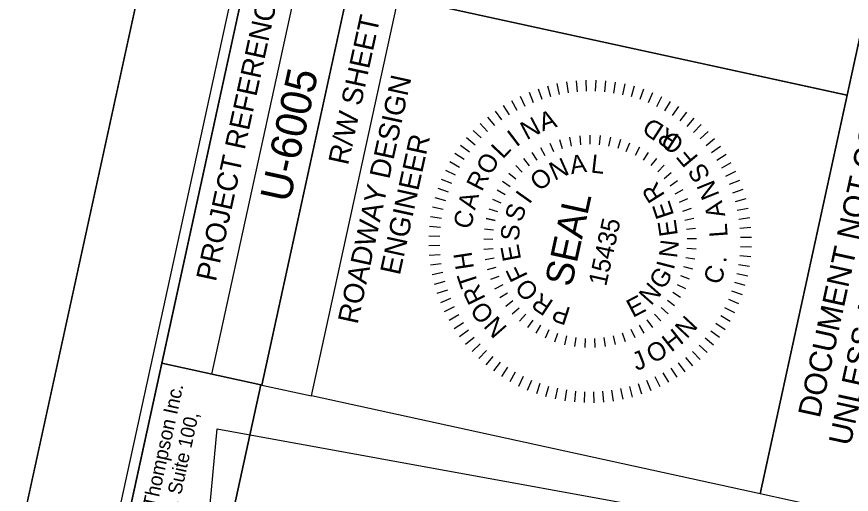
# Model space of a CAD drawing. Extents: x 1615716 to 1617263, y 900664 to 902742.
# Drawn here: x 1616130.6 to 1616335.1, y 902294.3 to 902411.4 of the extents above; entities that cross this region are included whole.
import ezdxf

# ---------------------------------------------------------------- set-up
doc = ezdxf.new("R2010")
doc.units = 0
for name, color, linetype in [('Default', 7, 'Continuous'), ('Exist Plan Preparation Watershed Blue', 7, 'Continuous'), ('Exist Structure Minor Pipes RCP 18 Inch', 7, 'Continuous'), ('Prop Drainage Structure Plot Symbol 20 Scale', 7, 'Continuous'), ('Prop EOT', 7, 'Continuous'), ('Prop SS Cut Line', 7, 'Continuous'), ('Prop SS Cut Text', 7, 'Continuous'), ('Prop SS Fill Line', 7, 'Continuous'), ('Prop SS Fill Text', 7, 'Continuous'), ('Prop SS Transition Line', 7, 'Continuous')]:
    doc.layers.add(name, color=color, linetype=linetype)

msp = doc.modelspace()

# ---------------------------------------------------------------- linework, layer by layer
at = {"layer": 'Default'}
msp.add_lwpolyline([(1616161.03, 902186.8), (1616190.38, 902321.16), (1616166.14, 902326.45), (1616136.79, 902192.09)], close=True, dxfattribs=at)
at = {"layer": 'Exist Plan Preparation Watershed Blue'}
for p, q in [((1616267.67, 902395.71), (1616267.9, 902393.02)), ((1616270.06, 902395.84), (1616270.13, 902393.15)), ((1616272.45, 902395.83), (1616272.35, 902393.14)), ((1616274.83, 902395.67), (1616274.57, 902392.99)), ((1616258.34, 902393.75), (1616259.21, 902391.2)), ((1616260.63, 902394.45), (1616261.34, 902391.85)), ((1616262.95, 902395.01), (1616263.5, 902392.37)), ((1616265.3, 902395.43), (1616265.7, 902392.76)), ((1616277.2, 902395.37), (1616276.78, 902392.71)), ((1616279.55, 902394.93), (1616278.97, 902392.3)), ((1616281.87, 902394.35), (1616281.13, 902391.76)), ((1616284.14, 902393.63), (1616283.25, 902391.08)), ((1616253.93, 902391.95), (1616255.09, 902389.52)), ((1616256.11, 902392.92), (1616257.13, 902390.42)), ((1616286.37, 902392.77), (1616285.33, 902390.29)), ((1616288.54, 902391.78), (1616287.35, 902389.36)), ((1616249.76, 902389.62), (1616251.21, 902387.35)), ((1616251.81, 902390.85), (1616253.12, 902388.49)), ((1616290.65, 902390.66), (1616289.32, 902388.32)), ((1616292.69, 902389.42), (1616291.21, 902387.16)), ((1616247.79, 902388.28), (1616249.37, 902386.1)), ((1616294.65, 902388.05), (1616293.04, 902385.88)), ((1616244.1, 902385.24), (1616245.94, 902383.27)), ((1616245.9, 902386.81), (1616247.61, 902384.73)), ((1616296.52, 902386.57), (1616294.79, 902384.5)), ((1616242.41, 902383.56), (1616244.36, 902381.7)), ((1616298.3, 902384.97), (1616296.44, 902383.02)), ((1616299.98, 902383.28), (1616298.01, 902381.44)), ((1616240.81, 902381.78), (1616242.88, 902380.04)), ((1616263.58, 902381.28), (1616264.23, 902379.13)), ((1616266.03, 902381.88), (1616266.46, 902379.68)), ((1616268.52, 902382.25), (1616268.73, 902380.01)), ((1616271.03, 902382.38), (1616271.03, 902380.13)), ((1616273.55, 902382.26), (1616273.33, 902380.02)), ((1616276.04, 902381.9), (1616275.61, 902379.69)), ((1616278.48, 902381.3), (1616277.85, 902379.14)), ((1616301.56, 902381.48), (1616299.48, 902379.77)), ((1616239.33, 902379.9), (1616241.49, 902378.3)), ((1616258.92, 902379.37), (1616259.97, 902377.39)), ((1616261.21, 902380.44), (1616262.06, 902378.36)), ((1616279.94, 902378.41), (1616280.78, 902380.49)), ((1616283.15, 902379.4), (1616282.11, 902377.42)), ((1616303.02, 902379.59), (1616300.84, 902378.01)), ((1616237.96, 902377.94), (1616240.22, 902376.47)), ((1616256.76, 902378.1), (1616257.99, 902376.22)), ((1616285.32, 902378.13), (1616284.09, 902376.25)), ((1616304.37, 902377.62), (1616302.1, 902376.17)), ((1616236.72, 902375.91), (1616239.06, 902374.57)), ((1616254.72, 902376.62), (1616256.13, 902374.86)), ((1616287.35, 902376.65), (1616285.95, 902374.9)), ((1616305.59, 902375.57), (1616303.24, 902374.26)), ((1616235.6, 902373.8), (1616238.02, 902372.61)), ((1616251.13, 902373.1), (1616252.84, 902371.65)), ((1616252.84, 902374.94), (1616254.41, 902373.34)), ((1616289.24, 902374.99), (1616287.68, 902373.38)), ((1616290.96, 902373.14), (1616289.25, 902371.69)), ((1616306.69, 902373.45), (1616304.27, 902372.28)), ((1616234.61, 902371.62), (1616237.09, 902370.58)), ((1616249.6, 902371.09), (1616251.45, 902369.82)), ((1616292.49, 902371.14), (1616290.65, 902369.87)), ((1616307.66, 902371.27), (1616305.17, 902370.25)), ((1616233.75, 902369.39), (1616236.29, 902368.51)), ((1616248.27, 902368.95), (1616250.24, 902367.86)), ((1616293.82, 902369.01), (1616291.86, 902367.91)), ((1616308.5, 902369.03), (1616305.95, 902368.16)), ((1616233.03, 902367.12), (1616235.62, 902366.38)), ((1616232.45, 902364.8), (1616235.08, 902364.22)), ((1616247.16, 902366.69), (1616249.22, 902365.8)), ((1616294.94, 902366.75), (1616292.88, 902365.85)), ((1616309.2, 902366.75), (1616306.6, 902366.04)), ((1616246.27, 902364.34), (1616248.41, 902363.65)), ((1616295.83, 902364.4), (1616293.7, 902363.7)), ((1616309.76, 902364.43), (1616307.12, 902363.88)), ((1616232, 902362.45), (1616234.67, 902362.03)), ((1616245.61, 902361.91), (1616247.8, 902361.43)), ((1616247.8, 902361.43), (1616245.61, 902361.91)), ((1616296.5, 902361.97), (1616294.3, 902361.48)), ((1616310.18, 902362.07), (1616307.51, 902361.68)), ((1616231.71, 902360.08), (1616234.39, 902359.83)), ((1616245.19, 902359.42), (1616247.42, 902359.16)), ((1616296.93, 902359.49), (1616294.69, 902359.21)), ((1616310.46, 902359.7), (1616307.77, 902359.47)), ((1616231.55, 902357.7), (1616234.24, 902357.61)), ((1616245.01, 902356.92), (1616247.26, 902356.86)), ((1616297.11, 902356.98), (1616294.86, 902356.92)), ((1616310.59, 902357.32), (1616307.89, 902357.25)), ((1616231.54, 902355.32), (1616234.23, 902355.38)), ((1616245.07, 902354.4), (1616247.32, 902354.56)), ((1616297.05, 902354.46), (1616294.81, 902354.62)), ((1616310.58, 902354.93), (1616307.88, 902355.03)), ((1616231.67, 902352.93), (1616234.36, 902353.16)), ((1616310.42, 902352.55), (1616307.74, 902352.81)), ((1616231.94, 902350.56), (1616234.61, 902350.95)), ((1616245.38, 902351.9), (1616247.59, 902352.28)), ((1616296.76, 902351.96), (1616294.54, 902352.34)), ((1616310.12, 902350.18), (1616307.46, 902350.6)), ((1616232.37, 902348.21), (1616235, 902348.76)), ((1616245.93, 902349.44), (1616248.09, 902350.03)), ((1616296.21, 902349.5), (1616294.05, 902350.09)), ((1616232.92, 902345.88), (1616235.53, 902346.6)), ((1616246.71, 902347.05), (1616248.81, 902347.84)), ((1616295.44, 902347.11), (1616293.34, 902347.9)), ((1616309.68, 902347.83), (1616307.05, 902348.41)), ((1616233.62, 902343.6), (1616236.18, 902344.47)), ((1616247.72, 902344.74), (1616249.73, 902345.74)), ((1616292.41, 902345.78), (1616294.43, 902344.78)), ((1616309.09, 902345.51), (1616306.5, 902346.25)), ((1616234.46, 902341.36), (1616236.95, 902342.38)), ((1616248.94, 902342.54), (1616250.85, 902343.73)), ((1616293.22, 902342.59), (1616291.3, 902343.78)), ((1616308.37, 902343.24), (1616305.83, 902344.13)), ((1616235.43, 902339.18), (1616237.86, 902340.35)), ((1616250.38, 902340.47), (1616252.16, 902341.84)), ((1616291.78, 902340.52), (1616290, 902341.88)), ((1616307.52, 902341.01), (1616305.03, 902342.05)), ((1616236.53, 902337.06), (1616238.88, 902338.37)), ((1616252, 902338.55), (1616253.65, 902340.08)), ((1616253.8, 902336.79), (1616255.3, 902338.47)), ((1616288.36, 902336.83), (1616286.87, 902338.51)), ((1616290.16, 902338.59), (1616288.52, 902340.12)), ((1616306.53, 902338.84), (1616304.11, 902340.02)), ((1616237.76, 902335.01), (1616240.03, 902336.46)), ((1616255.77, 902335.22), (1616257.09, 902337.03)), ((1616286.4, 902335.25), (1616285.08, 902337.07)), ((1616304.16, 902334.69), (1616301.9, 902336.17)), ((1616305.41, 902336.72), (1616303.06, 902338.06)), ((1616239.1, 902333.04), (1616241.28, 902334.63)), ((1616257.88, 902333.84), (1616259.01, 902335.78)), ((1616260.11, 902332.67), (1616261.05, 902334.71)), ((1616282.07, 902332.7), (1616281.12, 902334.73)), ((1616284.3, 902333.87), (1616283.16, 902335.8)), ((1616302.79, 902332.73), (1616300.63, 902334.34)), ((1616240.57, 902331.15), (1616242.64, 902332.87)), ((1616262.44, 902331.73), (1616263.18, 902333.84)), ((1616264.86, 902331.01), (1616265.39, 902333.19)), ((1616267.33, 902330.53), (1616267.65, 902332.75)), ((1616269.83, 902330.29), (1616269.94, 902332.53)), ((1616272.35, 902330.29), (1616272.24, 902332.53)), ((1616274.86, 902330.54), (1616274.53, 902332.76)), ((1616277.33, 902331.03), (1616276.79, 902333.2)), ((1616279.74, 902331.74), (1616278.99, 902333.86)), ((1616301.31, 902330.86), (1616299.25, 902332.59)), ((1616242.14, 902329.36), (1616244.11, 902331.19)), ((1616299.72, 902329.07), (1616297.77, 902330.93)), ((1616243.82, 902327.66), (1616245.68, 902329.61)), ((1616245.6, 902326.07), (1616247.34, 902328.13)), ((1616298.02, 902327.4), (1616296.19, 902329.37)), ((1616247.48, 902324.59), (1616249.08, 902326.75)), ((1616294.34, 902324.36), (1616292.75, 902326.54)), ((1616296.23, 902325.82), (1616294.51, 902327.9)), ((1616249.43, 902323.22), (1616250.91, 902325.47)), ((1616251.47, 902321.97), (1616252.81, 902324.32)), ((1616290.32, 902321.79), (1616289.01, 902324.14)), ((1616292.37, 902323.01), (1616290.92, 902325.28)), ((1616253.58, 902320.85), (1616254.77, 902323.27)), ((1616255.75, 902319.86), (1616256.8, 902322.35)), ((1616286.02, 902319.72), (1616285, 902322.21)), ((1616288.2, 902320.68), (1616287.03, 902323.11)), ((1616257.98, 902319.01), (1616258.87, 902321.55)), ((1616260.26, 902318.28), (1616260.99, 902320.88)), ((1616262.58, 902317.7), (1616263.15, 902320.33)), ((1616264.92, 902317.26), (1616265.34, 902319.92)), ((1616276.82, 902317.2), (1616276.43, 902319.87)), ((1616279.17, 902317.62), (1616278.62, 902320.26)), ((1616281.49, 902318.18), (1616280.78, 902320.78)), ((1616283.78, 902318.88), (1616282.91, 902321.43)), ((1616267.29, 902316.96), (1616267.55, 902319.64)), ((1616269.68, 902316.8), (1616269.77, 902319.49)), ((1616272.06, 902316.79), (1616272, 902319.48)), ((1616274.45, 902316.92), (1616274.22, 902319.61))]:
    msp.add_line(p, q, dxfattribs=at)
at = {"layer": 'Exist Structure Minor Pipes RCP 18 Inch'}
msp.add_lwpolyline([(1616136.79, 902192.09), (1616166.12, 902326.45), (1616190.38, 902321.16), (1616161.05, 902186.79)], close=True, dxfattribs=at)
at = {"layer": 'Prop Drainage Structure Plot Symbol 20 Scale'}
msp.add_lwpolyline([(1616850.42, 902379.94), (1617227.49, 902296.2), (1617121.36, 901790.43), (1617088.18, 901641.75), (1617042.44, 901522.26), (1617032.35, 901430.63), (1617021.35, 901334.38), (1616928.77, 900896.77), (1615902.83, 901120.28), (1615974.27, 901386.7), (1616087.67, 901888.92), (1616145.49, 901879.24), (1616184.12, 901827.49), (1616138.37, 901614.97), (1616150.59, 901618.07), (1616181.32, 901620.66), (1616299.19, 901764.2), (1616120.07, 901933.32), (1616161.35, 902112.51), (1616179.69, 902310.42), (1616338.57, 902281.41), (1616353.46, 902358.26)], close=True, dxfattribs=at)
at = {"layer": 'Prop EOT'}
for p, q in [((1616312.72, 902294.45), (1616355.38, 902489.89)), ((1616335.68, 902289.44), (1616312.72, 902294.45))]:
    msp.add_line(p, q, dxfattribs=at)
at = {"layer": 'Prop SS Cut Line'}
msp.add_line((1616187.99, 902543.84), (1615828.85, 900898.58), dxfattribs=at)
at = {"layer": 'Prop SS Cut Text'}
msp.add_lwpolyline([(1616208.96, 902534.66), (1615853.55, 900906.5), (1616884.38, 900681.48), (1617239.79, 902309.64)], close=True, dxfattribs=at)
at = {"layer": 'Prop SS Fill Line'}
for p, q in [((1616178.38, 902323.78), (1616221.05, 902519.22)), ((1616190.6, 902321.11), (1616233.26, 902516.56)), ((1616190.6, 902321.11), (1616233.26, 902516.56)), ((1616224.15, 902416.19), (1616334.01, 902392.21)), ((1616190.6, 902321.11), (1616202.81, 902318.44))]:
    msp.add_line(p, q, dxfattribs=at)
for points in [[(1616208.79, 902521.9), (1615888.89, 901056.41), (1616914.73, 900832.48), (1617234.63, 902297.97)], [(1616166.12, 902326.45), (1616208.79, 902521.9), (1616233.26, 902516.56), (1616190.6, 902321.11)], [(1616224.15, 902416.19), (1616245.47, 902513.89), (1616355.38, 902489.9), (1616334.06, 902392.2)], [(1616202.81, 902318.44), (1616224.15, 902416.19), (1616334.06, 902392.2), (1616312.72, 902294.45)]]:
    msp.add_lwpolyline(points, close=True, dxfattribs=at)
at = {"layer": 'Prop SS Fill Text'}
msp.add_lwpolyline([(1616187.99, 902543.84), (1615828.85, 900898.58), (1616903.54, 900663.99), (1617262.68, 902309.25)], close=True, dxfattribs=at)

# ---------------------------------------------------------------- texts
at = {"layer": 'Default'}
for s, height, p in [('Johnson, Mirmiran, & Thompson Inc.', 3.5139, (1616155.08, 902246.07)), ('4700 Falls of Neuse Rd, Suite 100, ', 3.4135, (1616160.12, 902244.97))]:
    msp.add_text(s, height=height, rotation=77.6785, dxfattribs=at).set_placement(p)
at = {"layer": 'Exist Plan Preparation Watershed Blue'}
for s, height, rotation, p in [('A', 4.49, 18.1235, (1616259.4, 902383.26)), ('N', 4.49, 27.891, (1616255.53, 902381.08)), (' RD', 4.488, 147.2788, (1616294.57, 902381.31)), ('I', 4.49, 37.1855, (1616252.98, 902379.34)), ('O ', 4.488, 138.6061, (1616294.45, 902380.66)), ('L', 4.49, 46.7609, (1616249.66, 902376.36)), ('O', 4.49, 59.8972, (1616246.73, 902372.33)), ('A', 4.49, 8.7733, (1616266.45, 902372.78)), ('L', 4.49, 353.477, (1616271.1, 902373.24)), ('F', 4.49, 129.8134, (1616297.79, 902376.94)), ('N', 4.49, 24.0695, (1616262.33, 902371.16)), ('S', 4.49, 120.9308, (1616300.7, 902372.47)), ('R', 4.49, 62.954, (1616244.53, 902368.36)), ('O', 4.49, 39.3658, (1616258.65, 902368.43)), ('R', 4.49, 122.1713, (1616289.56, 902367.64)), ('N', 4.49, 112.0482, (1616302.84, 902367.7)), ('A', 4.49, 74.9634, (1616242.87, 902363.86)), ('I', 4.49, 54.662, (1616256.17, 902365.27)), ('SEAL', 6.737, 77.6064, (1616266.5, 902344.96)), ('S', 4.49, 69.9583, (1616254.2, 902360.82)), ('E', 4.49, 108.4002, (1616291.7, 902362.79)), ('A', 4.49, 103.2256, (1616304.23, 902362.62)), ('C', 4.49, 74.9634, (1616241.73, 902359.09)), ('15435', 4.488, 77.6064, (1616274.99, 902345.16)), ('E', 4.49, 98.4143, (1616292.59, 902357.89)), ('S', 4.49, 85.2545, (1616253.6, 902356.36)), ('L', 4.49, 94.223, (1616304.8, 902357.53)), ('E', 4.49, 100.5508, (1616254.2, 902351.92)), ('N', 4.49, 83.0222, (1616292.34, 902352.12)), ('H', 4.49, 98.674, (1616242.63, 902349.74)), ('I', 4.49, 75.3926, (1616291.54, 902349.18)), ('.', 4.49, 81.4387, (1616304.37, 902350.94)), ('F', 4.49, 115.847, (1616255.91, 902347.86)), ('G', 4.49, 57.2978, (1616288.99, 902344.26)), ('C', 4.49, 73.6963, (1616303.05, 902345.52)), ('T', 4.49, 108.106, (1616243.76, 902345.8)), ('O', 4.49, 131.1432, (1616258.8, 902344.17)), ('R', 4.49, 116.267, (1616245.56, 902342.31)), ('N', 4.49, 48.5316, (1616285.99, 902340.42)), ('R', 4.49, 146.4395, (1616262.36, 902341.57)), ('E', 4.49, 27.6765, (1616281.53, 902337.55)), ('O', 4.49, 129.3237, (1616247.82, 902338.48)), ('P', 4.49, 161.7357, (1616266.56, 902339.95)), ('N', 4.49, 131.2831, (1616250.97, 902335.15)), ('N', 4.49, 46.9286, (1616294.76, 902332.27)), ('H', 4.49, 38.256, (1616290.95, 902329.03)), ('O', 4.49, 29.6132, (1616286.47, 902326.27)), ('J', 4.49, 21.5414, (1616282.43, 902324.53))]:
    msp.add_text(s, height=height, rotation=rotation, dxfattribs=at).set_placement(p)
at = {"layer": 'Prop EOT'}
for s, p in [('UNLESS ALL SIGNATURES COMPLETED', (1616334.84, 902306)), ('DOCUMENT NOT CONSIDERED FINAL', (1616327.32, 902312.83))]:
    msp.add_text(s, height=5.5, rotation=77.6862, dxfattribs=at).set_placement(p)
at = {"layer": 'Prop SS Fill Line'}
for s, height, p in [('PROJECT REFERENCE NO.', 5.0001, (1616179.36, 902346.29)), ('R/W SHEET NO.', 5.0001, (1616211.74, 902374.84)), ('ROADWAY DESIGN', 5.0001, (1616214.08, 902335.84)), ('ENGINEER', 5, (1616224.43, 902347.86))]:
    msp.add_text(s, height=height, rotation=77.6862, dxfattribs=at).set_placement(p)
at = {"layer": 'Prop SS Transition Line'}
msp.add_text('U-6005', height=7.5, rotation=77.6862, dxfattribs=at).set_placement((1616197.49, 902365.6))

doc.saveas('drawing.dxf')
